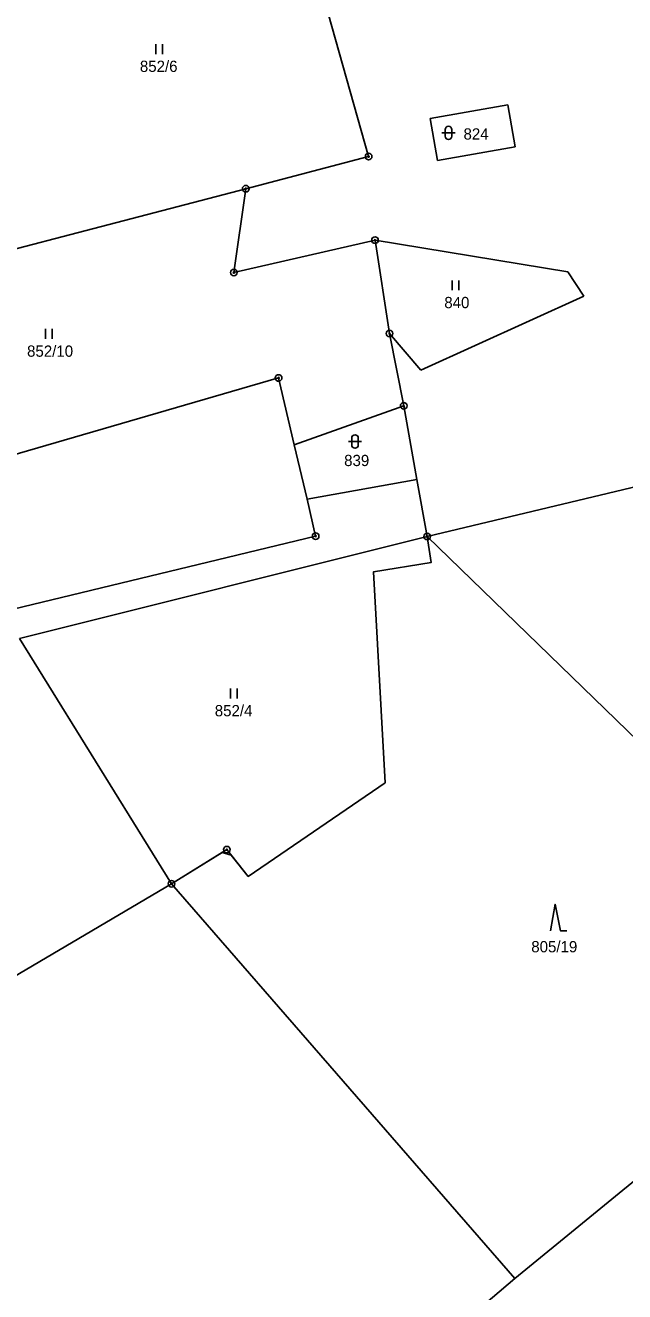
# Model space of a CAD drawing. Extents: x -439246 to -433691, y -1130252 to -1121148.
# Drawn here: x -438199.4 to -438109, y -1124733.9 to -1124542.5 of the extents above; entities that cross this region are included whole.
import ezdxf

# ---------------------------------------------------------------- set-up
doc = ezdxf.new("R2010")
doc.units = 0
for name, color, linetype in [('Vrstva 1', 7, 'Continuous'), ('Vrstva 18', 7, 'Continuous'), ('Vrstva 24', 7, 'Continuous'), ('Vrstva 25', 7, 'Continuous'), ('Vrstva 52', 7, 'Continuous'), ('Vrstva 6', 7, 'Continuous')]:
    doc.layers.add(name, color=color, linetype=linetype)

msp = doc.modelspace()

# ---------------------------------------------------------------- linework, layer by layer
at = {"layer": 'Vrstva 1'}
for points in [[(-438147.62, -1124562.36), (-438162.59, -1124509.29)], [(-438138.34, -1124556.6), (-438126.62, -1124554.55)], [(-438126.62, -1124554.55), (-438125.51, -1124560.91)], [(-438137.23, -1124562.96), (-438138.34, -1124556.6)], [(-438125.51, -1124560.91), (-438137.23, -1124562.96)], [(-438166.18, -1124567.21), (-438147.62, -1124562.36)], [(-438227.14, -1124583.16), (-438166.18, -1124567.21)], [(-438166.18, -1124567.21), (-438167.96, -1124579.88)], [(-438167.96, -1124579.88), (-438146.66, -1124574.99)], [(-438146.66, -1124574.99), (-438117.53, -1124579.75)], [(-438144.47, -1124589.09), (-438146.66, -1124574.99)], [(-438117.53, -1124579.75), (-438115.15, -1124583.47)], [(-438115.15, -1124583.47), (-438139.75, -1124594.62)], [(-438139.75, -1124594.62), (-438144.47, -1124589.09)], [(-438144.47, -1124589.09), (-438142.33, -1124600.03)], [(-438255.22, -1124623.13), (-438161.21, -1124595.81)], [(-438161.21, -1124595.81), (-438158.85, -1124605.91)], [(-438158.85, -1124605.91), (-438142.33, -1124600.03)], [(-438142.33, -1124600.03), (-438140.33, -1124611.17)], [(-438158.85, -1124605.91), (-438156.92, -1124614.14)], [(-438140.33, -1124611.17), (-438156.92, -1124614.14)], [(-438140.33, -1124611.17), (-438138.8, -1124619.75)], [(-438138.8, -1124619.75), (-438098.99, -1124610.24)], [(-438156.92, -1124614.14), (-438155.62, -1124619.7)], [(-438155.62, -1124619.7), (-438269.08, -1124647.09)], [(-438200.31, -1124635.18), (-438138.8, -1124619.75)], [(-438138.17, -1124623.67), (-438138.8, -1124619.75)], [(-438146.87, -1124625.08), (-438138.17, -1124623.67)], [(-438146.87, -1124625.08), (-438145.12, -1124656.95)], [(-438200.31, -1124635.18), (-438177.37, -1124672.22)], [(-438165.8, -1124671.12), (-438145.12, -1124656.95)], [(-438177.37, -1124672.22), (-438169.03, -1124667.07)], [(-438169.03, -1124667.07), (-438165.8, -1124671.12)], [(-438209.36, -1124691.09), (-438177.37, -1124672.22)]]:
    msp.add_lwpolyline(points, dxfattribs=at)
at = {"layer": 'Vrstva 24'}
for centre, radius in [((-438147.62, -1124562.36), 0.5), ((-438147.62, -1124562.36), 0.1), ((-438166.18, -1124567.21), 0.5), ((-438166.18, -1124567.21), 0.1), ((-438146.66, -1124574.99), 0.5), ((-438146.66, -1124574.99), 0.1), ((-438167.96, -1124579.88), 0.5), ((-438167.96, -1124579.88), 0.1), ((-438144.47, -1124589.09), 0.5), ((-438144.47, -1124589.09), 0.1), ((-438161.21, -1124595.81), 0.5), ((-438161.21, -1124595.81), 0.1), ((-438142.33, -1124600.03), 0.5), ((-438142.33, -1124600.03), 0.1), ((-438155.62, -1124619.7), 0.5), ((-438155.62, -1124619.7), 0.1), ((-438138.8, -1124619.75), 0.5), ((-438138.8, -1124619.75), 0.1), ((-438169.03, -1124667.07), 0.5), ((-438169.03, -1124667.07), 0.1), ((-438177.37, -1124672.22), 0.5), ((-438177.37, -1124672.22), 0.1)]:
    msp.add_circle(centre, radius, dxfattribs=at)
at = {"layer": 'Vrstva 25'}
for p, q in [((-438179.76, -1124546.87), (-438179.76, -1124545.37)), ((-438178.76, -1124546.87), (-438178.76, -1124545.37)), ((-438136.58, -1124558.79), (-438134.58, -1124558.79)), ((-438136.08, -1124559.29), (-438136.08, -1124558.29)), ((-438135.08, -1124558.29), (-438135.08, -1124559.29)), ((-438135, -1124582.56), (-438135, -1124581.06)), ((-438134, -1124582.56), (-438134, -1124581.06)), ((-438196.4, -1124589.9), (-438196.4, -1124588.4)), ((-438195.4, -1124589.9), (-438195.4, -1124588.4)), ((-438150.68, -1124605.42), (-438148.68, -1124605.42)), ((-438150.18, -1124605.92), (-438150.18, -1124604.92)), ((-438149.18, -1124604.92), (-438149.18, -1124605.92)), ((-438168.49, -1124644.22), (-438168.49, -1124642.72)), ((-438167.49, -1124644.22), (-438167.49, -1124642.72))]:
    msp.add_line(p, q, dxfattribs=at)
msp.add_lwpolyline([(-438120.18, -1124679.33), (-438119.48, -1124675.33), (-438118.68, -1124679.33), (-438117.68, -1124679.33)], dxfattribs=at)
for centre, start, end in [((-438135.58, -1124558.29), 0, 180), ((-438135.58, -1124559.29), 180, 0), ((-438149.68, -1124604.92), 0, 180), ((-438149.68, -1124605.92), 180, 0)]:
    msp.add_arc(centre, 0.5, start, end, dxfattribs=at)
at = {"layer": 'Vrstva 52'}
msp.add_lwpolyline([(-438287.01, -1124873.99), (-438274.1, -1124861.09), (-438234.61, -1124821.59), (-438252.83, -1124803.8), (-438257.17, -1124798.78), (-438258.08, -1124797.73), (-438212.2, -1124764.83), (-438220.76, -1124748.17), (-438221.65, -1124736.5), (-438213.18, -1124730.39), (-438215.1, -1124726.97), (-438219.14, -1124719.32), (-438219.66, -1124717.23), (-438207.9, -1124705.65), (-438209.36, -1124691.09), (-438177.37, -1124672.22), (-438169.73, -1124667.5), (-438168.37, -1124667.89), (-438165.8, -1124671.12), (-438145.12, -1124656.95), (-438146.87, -1124625.08), (-438138.17, -1124623.67), (-438138.8, -1124619.75), (-438098.99, -1124610.24)], dxfattribs=at)
at = {"layer": 'Vrstva 6'}
for points in [[(-438078.35, -1124678.43), (-438138.8, -1124619.75)], [(-438177.37, -1124672.22), (-438125.53, -1124731.84)], [(-438125.53, -1124731.84), (-438058.17, -1124676.72)], [(-438125.53, -1124731.84), (-438134.66, -1124739.61)]]:
    msp.add_lwpolyline(points, dxfattribs=at)

# ---------------------------------------------------------------- texts
at = {"layer": 'Vrstva 18'}
for s, p in [('852/6', (-438182.16, -1124549.57)), ('824', (-438133.3, -1124559.79)), ('840', (-438136.2, -1124585.26)), ('852/10', (-438199.19, -1124592.6)), ('839', (-438151.32, -1124609.12)), ('852/4', (-438170.85, -1124646.92)), ('805/19', (-438123.07, -1124682.58))]:
    msp.add_text(s, height=1.7, dxfattribs=at).set_placement(p)

doc.saveas('drawing.dxf')
